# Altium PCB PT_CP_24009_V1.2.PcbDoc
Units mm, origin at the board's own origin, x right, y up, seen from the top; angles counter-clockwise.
Board outline 64.54 x 121.46 mm, 2 copper layers (Top Layer, Bottom Layer); 84 components, 67 nets, 226 pads, 45 vias.
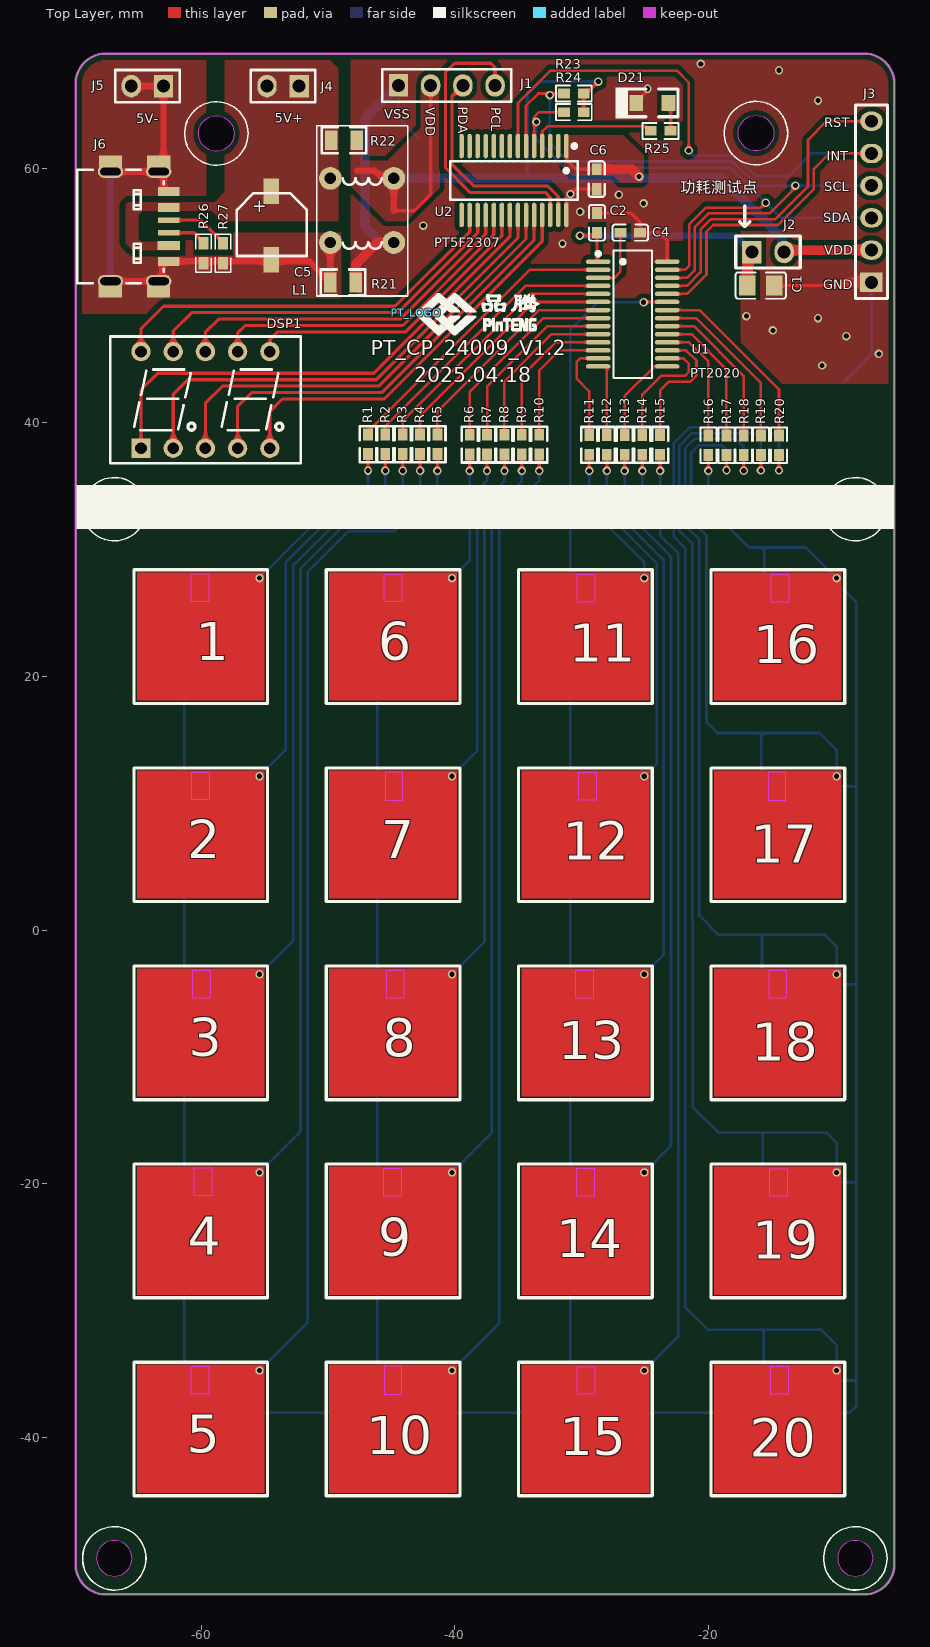
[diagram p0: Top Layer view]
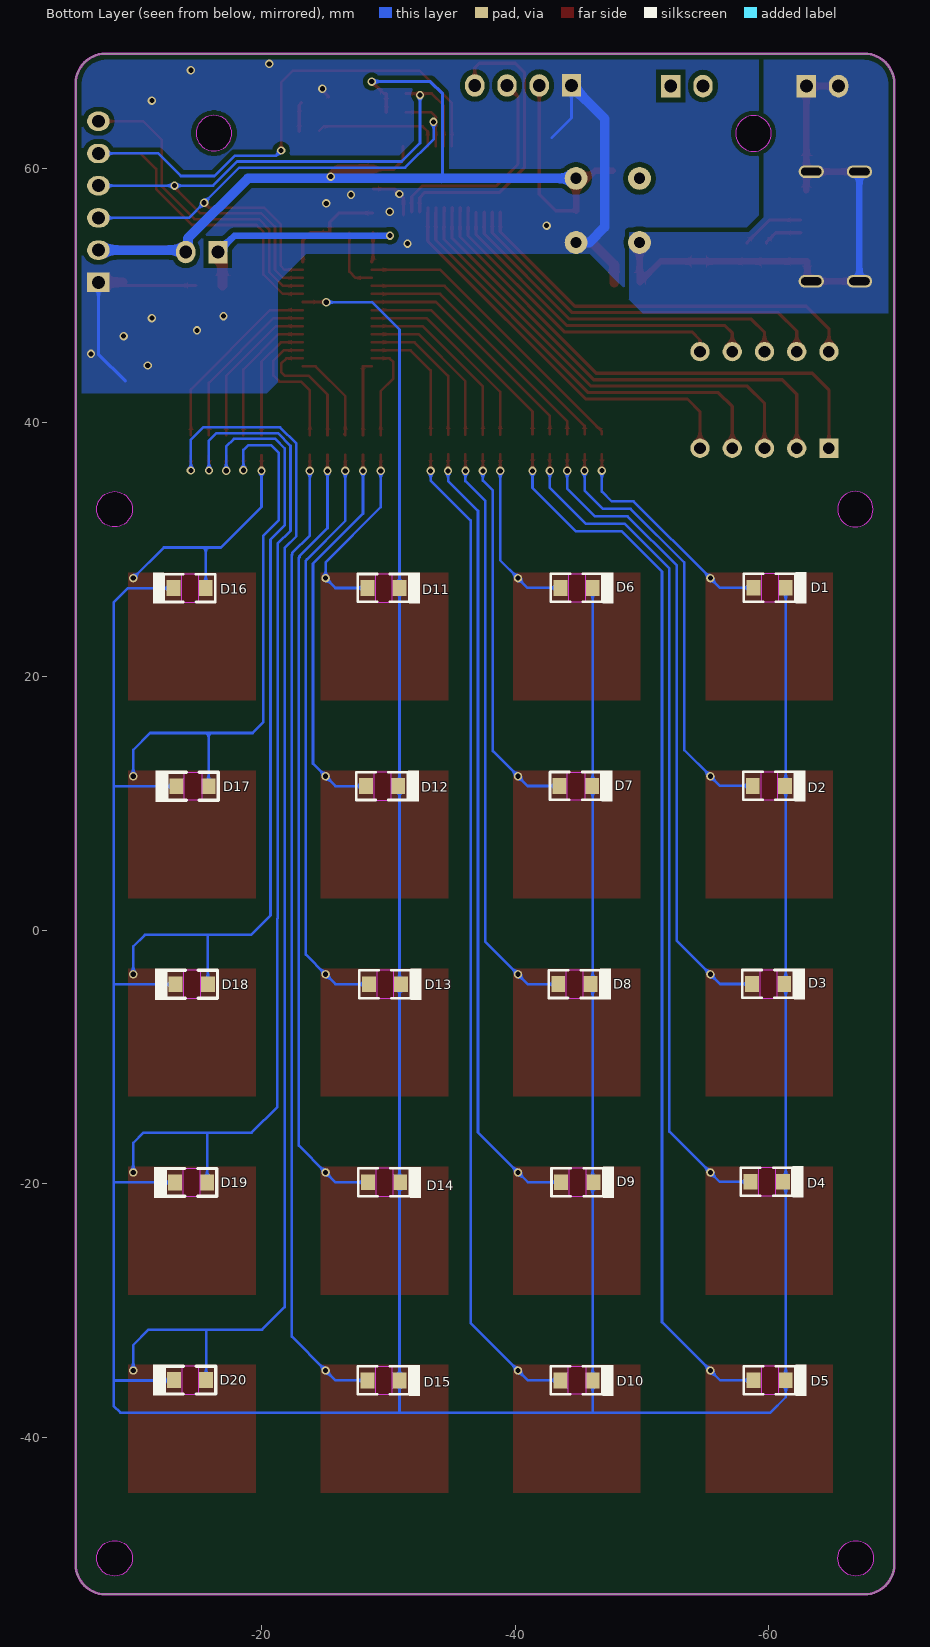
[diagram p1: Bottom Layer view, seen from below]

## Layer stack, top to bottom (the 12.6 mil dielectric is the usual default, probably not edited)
Top Solder: solder mask 0.0102, Solder Resist, Dk 3.5
Top Layer: signal copper 0.0356
Dielectric 1: dielectric 0.32, FR-4, Dk 4.8
Bottom Layer: signal copper 0.0356
Bottom Solder: solder mask 0.0102, Solder Resist, Dk 3.5

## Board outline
-69.901,-49.987 -69.901,66.7 cw(c-67.513,66.7) -67.513,69.088 -7.747,69.088 cw(c-7.747,66.7) -5.359,66.7 -5.359,-49.987 cw(c-7.747,-49.987) -7.747,-52.375 -67.513,-52.375 cw(c-67.513,-49.987)
cut-out: -60.782,25.868 -60.782,28.068 -59.411,28.068 -59.411,25.868
cut-out: -45.559,25.862 -45.559,28.062 -44.187,28.062 -44.187,25.862
cut-out: -30.336,25.855 -30.336,28.056 -28.964,28.056 -28.964,25.855
cut-out: -15.062,25.849 -15.062,28.049 -13.69,28.049 -13.69,25.849
cut-out: -60.723,10.254 -60.723,12.454 -59.351,12.454 -59.351,10.254
cut-out: -45.5,10.247 -44.128,10.247 -44.128,12.447 -45.5,12.447
cut-out: -30.226,10.241 -30.226,12.441 -28.854,12.441 -28.854,10.241
cut-out: -15.291,10.228 -13.919,10.228 -13.919,12.428 -15.291,12.428
cut-out: -60.664,-5.361 -60.664,-3.161 -59.292,-3.161 -59.292,-5.361
cut-out: -45.39,-5.367 -45.39,-3.167 -44.018,-3.167 -44.018,-5.367
cut-out: -30.454,-5.38 -30.454,-3.18 -29.083,-3.18 -29.083,-5.38
cut-out: -15.231,-5.386 -15.231,-3.186 -13.86,-3.186 -13.86,-5.386
cut-out: -60.553,-20.95 -60.553,-18.75 -59.182,-18.75 -59.182,-20.95
cut-out: -45.618,-20.989 -45.618,-18.788 -44.247,-18.788 -44.247,-20.989
cut-out: -30.395,-20.995 -30.395,-18.795 -29.024,-18.795 -29.024,-20.995
cut-out: -15.172,-21.001 -15.172,-18.801 -13.801,-18.801 -13.801,-21.001
cut-out: -60.782,-36.597 -60.782,-34.397 -59.411,-34.397 -59.411,-36.597
cut-out: -45.559,-36.603 -44.187,-36.603 -44.187,-34.403 -45.559,-34.403
cut-out: -30.336,-36.61 -30.336,-34.41 -28.964,-34.41 -28.964,-36.61
cut-out: -15.087,-36.59 -15.087,-34.39 -13.716,-34.39 -13.716,-36.59
cut-out: -66.827,31.772 cw(c-66.827,33.172) -68.227,33.172 cw(c-66.827,33.172) -66.827,34.572 cw(c-66.827,33.172) -65.427,33.172 cw(c-66.827,33.172)
cut-out: -9.833,33.172 ccw(c-8.433,33.172) -8.433,31.772 ccw(c-8.433,33.172) -7.033,33.172 ccw(c-8.433,33.172) -8.433,34.572 ccw(c-8.433,33.172)
cut-out: -58.801,61.389 cw(c-58.801,62.789) -60.201,62.789 cw(c-58.801,62.789) -58.801,64.189 cw(c-58.801,62.789) -57.401,62.789 cw(c-58.801,62.789)
cut-out: -16.267,61.414 cw(c-16.267,62.814) -17.667,62.814 cw(c-16.267,62.814) -16.267,64.214 cw(c-16.267,62.814) -14.867,62.814 cw(c-16.267,62.814)
cut-out: -68.25,-49.53 ccw(c-66.85,-49.53) -66.85,-50.93 ccw(c-66.85,-49.53) -65.45,-49.53 ccw(c-66.85,-49.53) -66.85,-48.13 ccw(c-66.85,-49.53)
cut-out: -9.833,-49.53 ccw(c-8.433,-49.53) -8.433,-50.93 ccw(c-8.433,-49.53) -7.033,-49.53 ccw(c-8.433,-49.53) -8.433,-48.13 ccw(c-8.433,-49.53)

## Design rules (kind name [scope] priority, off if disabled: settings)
Clearance [All] p1: gap=0.381
PolygonConnect [All] p1: connectstyle=Direct reliefconductorwidth=0.254 reliefentries=4 polygonreliefangle="90 Angle" airgapwidth=0.254
RoutingVias [All] p1: holewidth=0.711 width=1.27 viastyle="Through Hole" minholewidth=0.711 minwidth=1.27 maxholewidth=0.711 maxwidth=1.27
SolderMaskExpansion [All] p1: expansion=0.102
SupplyNets "Schematic Supply Nets_3" [InNet('GND')] p1: voltage=0.000
SupplyNets "Schematic Supply Nets_2" [InNet('IGND')] p2: voltage=0.000
SupplyNets "Schematic Supply Nets_1" [InNet('5V')] p3: voltage=0.000
SupplyNets "Schematic Supply Nets" [InNet('VIN')] p4: voltage=0.000
Width [All] p1: maxlimit=2.54 minlimit=0.203 preferedwidth=0.203
30 further rules are at their usual default settings.

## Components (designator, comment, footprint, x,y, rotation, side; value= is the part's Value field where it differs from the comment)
1 "DOWN" "TP_10mm - H" -60.046,23.165 r0 top
2 "DOWN" "TP_10mm - H" -60.046,7.55 r0 top
3 "DOWN" "TP_10mm - H" -60.046,-8.065 r0 top
4 "DOWN" "TP_10mm - H" -60.046,-23.679 r0 top
5 "DOWN" "TP_10mm - H" -60.046,-39.294 r0 top
6 "DOWN" "TP_10mm - H" -44.882,23.165 r0 top
7 "DOWN" "TP_10mm - H" -44.882,7.55 r0 top
8 "DOWN" "TP_10mm - H" -44.882,-8.065 r0 top
9 "DOWN" "TP_10mm - H" -44.882,-23.679 r0 top
10 "DOWN" "TP_10mm - H" -44.882,-39.294 r0 top
11 "DOWN" "TP_10mm - H" -29.718,23.165 r0 top
12 "DOWN" "TP_10mm - H" -29.718,7.55 r0 top
13 "DOWN" "TP_10mm - H" -29.718,-8.065 r0 top
14 "DOWN" "TP_10mm - H" -29.718,-23.679 r0 top
15 "DOWN" "TP_10mm - H" -29.718,-39.294 r0 top
16 "DOWN" "TP_10mm - H" -14.554,23.165 r0 top
17 "DOWN" "TP_10mm - H" -14.554,7.55 r0 top
18 "DOWN" "TP_10mm - H" -14.554,-8.065 r0 top
19 "DOWN" "TP_10mm - H" -14.554,-23.679 r0 top
20 "DOWN" "TP_10mm - H" -14.554,-39.294 r0 top
C1 "10uF" C0805 -16.942,50.8 r0 top
C2 "0.1uF" C0603 -28.804,54.966 r90 top
C4 "20nF" C0603 -25.4,54.966 r180 top
C5 "100uF/16V" CS5.0 -54.483,58.232 r90 top
C6 "0.1uF" C0603 -28.829,59.969 r270 top
D1 "LED_B" LED_0805_F -58.801,26.975 r180 bottom
D2 "LED_B" LED_0805_F -58.742,11.36 r180 bottom
D3 "LED_B" LED_0805_F -58.682,-4.254 r180 bottom
D4 "LED_B" LED_0805_F -58.572,-19.844 r180 bottom
D5 "LED_B" LED_0805_F -58.801,-35.49 r180 bottom
D6 "LED_B" LED_0805_F -43.578,26.968 r180 bottom
D7 "LED_B" LED_0805_F -43.519,11.354 r180 bottom
D8 "LED_B" LED_0805_F -43.409,-4.261 r180 bottom
D9 "LED_B" LED_0805_F -43.637,-19.882 r180 bottom
D10 "LED_B" LED_0805_F -43.578,-35.497 r180 bottom
D11 "LED_B" LED_0805_F -28.355,26.962 r180 bottom
D12 "LED_B" LED_0805_F -28.245,11.347 r180 bottom
D13 "LED_B" LED_0805_F -28.473,-4.274 r180 bottom
D14 "LED_B" LED_0805_F -28.414,-19.889 r180 bottom
D15 "LED_B" LED_0805_F -28.355,-35.503 r180 bottom
D16 "LED_B" LED_0805_F -15.621,26.955 r0 bottom
D17 "LED_B" LED_0805_F -15.85,11.335 r0 bottom
D18 "LED_B" LED_0805_F -15.79,-4.28 r0 bottom
D19 "LED_B" LED_0805_F -15.731,-19.895 r0 bottom
D20 "LED_B" LED_0805_F -15.646,-35.484 r0 bottom
D21 "LED_B" LED_0805 -23.165,65.202 r180 top
DSP1 "CS2821AS" LED_2_0.28_2281 -64.745,37.973 r0 top
J1 "4PIN" D2.54_4P -44.45,66.573 r0 top
J2 "2PIN" D2.54_2P -16.586,53.442 r0 top
J3 "6PIN" D2.54_6P -7.163,51.054 r90 top
J4 "2PIN" D2.54_2P -52.273,66.523 r180 top
J5 "2PIN" D2.54_2P -62.967,66.523 r180 top
J6 "Type-C母座" TYPE-C-6P -65.251,55.458 r90 top
L1 "NC" L_10*5 -44.814,54.195 r180 top
PT_LOGO "PT_LOGO" PT_LOGO_2 -43.053,48.641 r0 top
R1 "470R" R0603 -46.849,37.516 r90 top
R2 "470R" R0603 -45.481,37.516 r90 top
R3 "470R" R0603 -44.113,37.516 r90 top
R4 "470R" R0603 -42.745,37.516 r90 top
R5 "470R" R0603 -41.377,37.516 r90 top
R6 "470R" R0603 -38.837,37.49 r90 top
R7 "470R" R0603 -37.465,37.49 r90 top
R8 "470R" R0603 -36.093,37.49 r90 top
R9 "470R" R0603 -34.722,37.49 r90 top
R10 "470R" R0603 -33.35,37.49 r90 top
R11 "470R" R0603 -29.413,37.465 r90 top
R12 "470R" R0603 -28.016,37.465 r90 top
R13 "470R" R0603 -26.619,37.465 r90 top
R14 "470R" R0603 -25.222,37.465 r90 top
R15 "470R" R0603 -23.825,37.465 r90 top
R16 "470R" R0603 -20.015,37.44 r90 top
R17 "470R" R0603 -18.593,37.44 r90 top
R18 "470R" R0603 -17.234,37.44 r90 top
R19 "470R" R0603 -15.875,37.44 r90 top
R20 "470R" R0603 -14.453,37.44 r90 top
R21 "0R" R0805 -49.818,51.045 r0 top
R22 "0R" R0805 -49.733,62.255 r0 top
R23 "470R" R0603 -31.394,65.938 r0 top
R24 "470R" R0603 -31.394,64.465 r0 top
R25 "470R" R0603 -24.562,62.992 r0 top
R26 "5.1K" RES0603 -59.817,53.34 r90 top
R27 "5.1K" RES0603 -58.293,53.34 r90 top
U1 "PT2020P28" SSOP28_0.635 -28.702,52.68 r270 top
U2 "PT5F2306P28" SSOP28_0.635 -31.217,61.798 r180 top

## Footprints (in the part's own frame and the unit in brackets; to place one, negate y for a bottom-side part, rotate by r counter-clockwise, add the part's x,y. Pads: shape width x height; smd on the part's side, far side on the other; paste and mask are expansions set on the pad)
C0603 [mil]
  rect 36.69x30 smd: 1(0,0) 2(61,0)
  silkscreen extent -25,-25 86,25
C0805 [mm]
  rect 1.3x1.55 smd: 1(0,0) 2(2.102,0)
  silkscreen extent -0.93,-1.04 3.03,1.04
CS5.0 [mm] "贴片电解电容"
  rect 2x1.2 smd: 1(0,0) 2(-5.4,0)
  silkscreen extent -5.1,-2.8 -0.15,2.71
D2.54_2P [mil] "接线端子"
  rect 60x70 hole 40: 1(0,0)
  oval 60x70 hole 40: 2(100,0)
  silkscreen extent -50,-50 150,50
D2.54_4P [mil] "接线端子"
  rect 60x70 hole 40: 1(0,0)
  oval 60x70 hole 40: 2(100,0) 3(200,0) 4(300,0)
  silkscreen extent -50,-50 350,50
D2.54_6P [mil] "接线端子"
  rect 60x70 hole 40: 1(0,0)
  oval 60x70 hole 40: 2(100,0) 3(200,0) 4(300,0) 5(400,0) 6(500,0)
  silkscreen extent -50,-50 550,50
L_10*5 [mm] "共模电感"
  round 1.8 hole 0.889: 1(0,0) 2(5,0) 3(0,-5.055) 4(5,-5.055)
  silkscreen extent -1.09,-9.19 6.07,4.22
LED_2_0.28_2281 [mil] "2*8数码管"
  rect 60x60 hole 36 mask+2: 1(0,0)
  round 60 hole 36 mask+2: 2(100,0) 3(200,0) 4(300,0) 5(400,0) 6(400,300) 7(300,300) 8(200,300) 9(100,300) 10(0,300)
  silkscreen extent -95,-47 495,347
LED_0805 [mm]
  rect 1.1x1.25 smd mask+0.051: 1(0,0) 2(2.54,0)
  silkscreen extent -0.76,-1.23 4.17,1.23
LED_0805_F [mm]
  rect 1.1x1.25 smd mask+0.051: 1(0,0) 2(2.54,0)
  silkscreen extent -0.76,-1.23 4.17,1.23
PT_LOGO_2 [mm]
  silkscreen extent 0,-1.73 9.7,1.55
R0603 [mil]
  rect 36.69x30 smd: 1(0,0) 2(61,0)
  silkscreen extent -25,-25 86,25
R0805 [mm]
  rect 1x1.55 smd: 1(0,0) 2(2,0)
  silkscreen extent -0.75,-1.02 2.75,1.02
RES0603 [mil]
  rect 38x31 smd: 1(-31,0) 2(31,0)
  silkscreen extent -59,-24 59,24, body extent -30,-15 33,16, height 18
SSOP28_0.635 [mil]
  oval 14x76.17 smd: 1(0,0) 2(25,0) 3(50,0) 4(75,0) 5(100,0) 6(125,0) 7(150,0) 8(175,0) 9(200,0) 10(225,0) 11(250,0) 12(275,0) 13(300,0) 14(325,0) 15(325,213.93) 16(300,213.93) 17(275,213.93) 18(250,213.93) 19(225,213.93) 20(200,213.93) 21(175,213.93) 22(150,213.93) 23(125,213.93) 24(100,213.93) 25(75,213.93) 26(50,213.93) 27(25,213.93) 28(0,213.93)
  silkscreen extent -35,-6 360,167
"TP_10mm - H" [mil]
  round 26 hole 16: 1(183,180)
  Top Layer region: -197,-199 -197,197.5 198,197.5 198,-199
  silkscreen extent -207,-209 208,206
TYPE-C-6P [mm]
  rect 1.016x1.829 smd: 0(-5.073,-1.885) 0(-5.073,1.915) 0(5.073,-1.915) 0(5.073,1.885)
  oval 1x2 hole 0.6 slot 1.6 at 90 deg: 0(-4.32,-1.9) 0(-4.32,1.9) 0(4.32,-1.9) 0(4.32,1.9)
  rect 0.45x1.7 smd: A5(0.5,-2.7) B5(-0.5,-2.7)
  rect 0.7x1.8 smd: A9(-1.5,-2.7)
  rect 0.7x1.7 smd: A12(-2.75,-2.7) B9(1.5,-2.7) B12(2.75,-2.7)
  silkscreen extent -4.47,-2.3 4.47,4.5

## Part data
1 2 3 4 5 6 7 8 9 10 11 12 13 14 15 16 17 18 19 20: library part TOUCH_SM, "TP"
C1 C2 C4: library part CAP3
C5: library part CAP2, "电解电容"
C6: library part CAP1, "电容"
D1 D2 D3 D4 D5 D6 D7 D8 D9 D10 D11 D12 D13 D14 D15 D16 D17 D18 D19 D20 D21: library part LED
DSP1: library part LED_2, "2位数码管"
J6: library part Type-C-receptacle_6p, "Type-C 6P直插"
L1: library part "Trans Cupl", "Transformer (Coupled Inductor Model)"
R1 R2 R3 R4 R5 R6 R7 R8 R9 R10 R11 R12 R13 R14 R15 R16 R17 R18 R19 R20 R21 R22 R23 R24 R25: library part RES1, "电阻"
R26 R27: library part Res, "Resistor"
U1: "20键标品"
U2: library part PT109AP28, "MCU"

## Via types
v1: diameter 0.66, hole 0.406, Top Layer to Bottom Layer, tented both sides, 45 vias

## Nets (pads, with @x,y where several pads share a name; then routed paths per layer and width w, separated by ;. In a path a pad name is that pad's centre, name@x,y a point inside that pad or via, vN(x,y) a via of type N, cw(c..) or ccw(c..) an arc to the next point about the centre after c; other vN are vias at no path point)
5V: C6.1 J1.2 J2.2 J3.2 L1.3 R22.2 R23.2 R24.2 U2.1 | length 87.5
  Top Layer w0.254: -44.814,56.695 -43.203,56.695 -41.91,57.988 J1.2 ; U2.1@-31.166,61.798 -31.166,60.725 -31.188,60.703 -30.455,59.969 C6.1 ; R24.2 R23.2 -29.642,65.938 v1(-28.702,66.878)
  Top Layer w0.508: -47.716,59.859 -46.321,59.859 -44.814,58.352 -44.814,56.695
  Top Layer w0.762: C6.1 -26.06,59.969 v1(-25.476,59.385) ; J2.2@-14.021,53.823 -13.792,53.594 J3.2
  Bottom Layer w0.254: -34.239,59.249 -34.29,59.3 -34.29,65.913 -33.325,66.878 v1(-28.702,66.878)
  Bottom Layer w0.762: L1.3 -34.239,59.249 -18.94,59.249 -14.224,54.534 -14.224,54.026 -13.792,53.594 J3.2
CC1: J6.A5 R27.2 | length 5.1
  Top Layer w0.254: J6.A5 -60.035,55.958 -58.293,54.216 R27.2
CC2: J6.B5 R26.2 | length 3.1
  Top Layer w0.254: J6.B5 -60.559,54.958 -59.817,54.216 R26.2
GND: C1.2 C2.2 C4.1 C6.2 D21.2 J1.1 J3.1 L1.1 R21.2 U1.28 U2.28 | length 56.7
  Top Layer w0.203: D21.2@-25.324,65.659 v1@-24.74,66.243
  Top Layer w0.254: U2.28 -31.217,57.683 v1(-30.886,58.014) -30.48,58.42 C6.2 ; C2.2 -26.111,56.515 -25.4,55.804 C4.1 -23.876,54.966 -23.268,54.358 U1.28 ; C1.2 -7.417,50.8 J3.1
  Top Layer w0.762: R21.2 -47.818,52.461 -46.084,54.195 L1.1 ; -9.068,51.054 J3.1
  Bottom Layer w0.203: J1.1 -44.45,64.008 -42.901,62.459
  Bottom Layer w0.254: -9.271,43.282 -7.163,45.39 J3.1
  Bottom Layer w0.762: L1.1 -45.864,54.195 -47.066,55.397 -47.066,63.957 J1.1
  other v1: -11.049,44.501 -6.579,45.415 -9.144,46.812 -14.935,47.269 -11.379,48.235 -17.018,48.387 -31.521,54.102 -42.494,55.524 -30.124,56.617 -25.121,57.277 -27.076,57.963 -11.379,65.38 -24.816,66.319 -14.453,67.767 -20.625,68.275
I2C_SCL: J3.4 R23.1 U1.26 U2.6 | length 53.2
  Top Layer w0.203: U2.6 -34.392,64.973 -33.426,65.938 R23.1 ; U1.26 -21.717,51.41 -21.082,52.045 -21.082,55.421 -20.013,56.49 -15.215,56.49 -13.157,58.547 v1(-13.157,58.674)
  Bottom Layer w0.203: v1(-32.512,65.811) -32.512,62.027 -31.064,60.579 -18.099,60.579 -16.194,58.674 -12.243,58.674 ; v1(-13.157,58.674) -12.243,58.674 ; J3.4 -12.243,58.674
I2C_SDA: J3.3 R24.1 U1.27 U2.5 | length 47
  Top Layer w0.203: U2.5 -33.757,64.084 -33.376,64.465 R24.1 ; U1.27 -21.844,52.045 -21.539,52.349 -21.539,55.61 -20.202,56.947 -15.875,56.947 v1(-15.494,57.328)
  Bottom Layer w0.203: v1(-33.579,63.703) -33.579,62.332 -31.344,60.096 -18.263,60.096 v1(-15.494,57.328) -14.3,56.134 J3.3
IGND: C5.2 J5.1 J5.2 J6.0 J6.A12 J6.B12 L1.2 R21.1 R26.1 R27.1 | length 46
  Top Layer w0.508: J6.0@-67.151,51.138 -65.557,51.138 -63.451,51.138 -63.051,51.538 -63.051,52.708 -60.452,52.708 -59.69,52.708 -58.928,52.708 -58.547,52.708 -57.556,52.708 -54.737,52.708 -51.481,52.708 R21.1 -49.818,54.191 L1.2 ; J6.0@-67.151,59.778 -63.451,59.778 J6.0@-63.082,59.778 ; J5.2 J5.1 J6.B12@-62.967,58.293
  Bottom Layer w0.508: J6.0@-67.151,51.138 J6.0@-67.151,59.778
INT: J3.5 U1.24 U2.7 | length 63.2
  Top Layer w0.203: U2.7 -35.027,65.176 -32.461,67.742 -22.504,67.742 -21.565,66.802 v1(-21.565,61.443) ; U1.24 -21.692,50.14 -20.168,51.664 -20.168,55.042 -19.634,55.575 -14.543,55.575 -11.709,58.408 -11.709,59.995 -10.49,61.214 J3.5
  Bottom Layer w0.203: v1(-21.565,61.443) -21.158,61.036 -17.909,61.036 -16.309,59.436 -13.665,59.436 -11.887,61.214 J3.5
LED_A: DSP1.7 U2.19 | length 26.7
  Top Layer w0.254: DSP1.7 -57.125,47.066 -56.54,47.65 -44.087,47.65 -36.932,54.806 U2.19@-36.932,56.593
LED_B: DSP1.8 U2.18 | length 28.5
  Top Layer w0.254: DSP1.8 -59.665,47.117 -58.623,48.158 -44.298,48.158 -37.567,54.889 U2.18@-37.567,56.593
LED_C: DSP1.3 U2.23 | length 36.7
  Top Layer w0.254: DSP1.3 -59.665,41.529 -58.318,42.875 -45.989,42.875 -34.392,54.472 U2.23@-34.392,56.593 ; U2.23@-34.417,56.593 U2.23@-34.417,56.949
LED_COM: D1.2 D2.2 D3.2 D4.2 D5.2 D6.2 D7.2 D8.2 D9.2 D10.2 D11.2 D12.2 D13.2 D14.2 D15.2 D16.2 D17.2 D18.2 D19.2 D20.2 U1.23 | length 364.2
  Top Layer w0.203: v1@-25.095,49.505 U1.23
  Bottom Layer w0.203: D1.2 D5.2 -61.341,-36.83 -60.122,-38.049 -8.89,-38.049 -8.357,-37.516 -8.357,11.354 ; -46.118,-38.041 D6.2 ; -30.895,-38.032 D11.2 -30.895,47.337 -28.753,49.479 v1(-25.121,49.479) ; D17.2 -8.376,11.335 -8.357,11.354 ; D18.2 -8.395,-4.28 ; D19.2 -8.414,-19.895 ; D20.2 -13.106,-35.509 -8.382,-35.509 ; D16.2 -13.075,26.949 -9.5,26.949 -8.357,25.806 -8.357,11.354
LED_D: DSP1.2 U2.22 | length 38.9
  Top Layer w0.254: DSP1.2 -62.205,42.24 -61.062,43.383 -46.199,43.383 -35.027,54.556 U2.22@-35.027,56.593 ; U2.22@-35.052,56.593 U2.22@-35.052,56.949
LED_DP: DSP1.5 U2.25 | length 32.6
  Top Layer w0.254: DSP1.5 -54.585,40.869 -53.594,41.859 -45.568,41.859 -33.122,54.305 U2.25@-33.122,56.593 ; U2.25@-33.147,56.593 U2.25@-33.147,56.949
LED_E: DSP1.1 U2.21 | length 41
  Top Layer w0.254: DSP1.1 -64.745,42.57 -63.424,43.891 -46.41,43.891 -35.662,54.639 U2.21@-35.662,56.593 ; U2.21@-35.687,56.593 U2.21@-35.687,56.949
LED_F: DSP1.10 U2.16 | length 32.4
  Top Layer w0.254: DSP1.10 -64.745,47.396 -62.967,49.174 -44.718,49.174 -38.837,55.056 U2.16@-38.837,56.593
LED_G: DSP1.4 U2.24 | length 34.7
  Top Layer w0.254: DSP1.4 -57.125,41.275 -56.032,42.367 -45.778,42.367 -33.757,54.389 U2.24@-33.757,56.593 ; U2.24@-33.782,56.593 U2.24@-33.782,56.949
LED_G1: DSP1.9 U2.17 | length 30.5
  Top Layer w0.254: DSP1.9 -62.205,47.219 -60.757,48.666 -44.508,48.666 -38.202,54.973 U2.17@-38.202,56.593
LED_G2: DSP1.6 U2.20 | length 24.8
  Top Layer w0.254: DSP1.6 -54.585,46.507 -53.95,47.142 -43.877,47.142 -36.297,54.723 U2.20@-36.297,56.593 ; U2.20@-36.322,56.593 U2.20@-36.322,56.949
MCU_RX0: J1.4 U2.26 | length 23.7
  Top Layer w0.254: J1.4 -36.83,67.97 -37.186,68.326 -40.03,68.326 -40.742,67.615 -40.742,60.071 -38.811,58.141 -32.893,58.141 -32.487,57.734 U2.26@-32.487,56.593
MCU_TX0: J1.3 U2.27 | length 17.6
  Top Layer w0.254: J1.3@-39.37,66.192 J1.3 -40.234,65.71 -40.234,60.376 -38.506,58.649 -32.683,58.649 -31.852,57.818 U2.27@-31.852,56.593
Net1_1: 1.1 D1.1 R1.1 | length 18.1
  Top Layer w0.203: v1(-46.849,36.209) R1.1
  Bottom Layer w0.203: D1.1 -56.159,26.975 1.1 -49.352,33.782 -47.625,33.782 -46.849,34.558 v1(-46.849,36.209)
Net2_1: 2.1 D2.1 R2.1 | length 34.4
  Top Layer w0.203: v1(-45.481,36.206) R2.1
  Bottom Layer w0.203: D2.1 -56.159,11.36 2.1 -53.34,14.18 -53.34,28.968 -49.11,33.198 -46.943,33.198 -45.481,34.66 v1(-45.481,36.206)
Net3_1: 3.1 D3.1 R3.1 | length 50.8
  Top Layer w0.203: v1(-44.113,36.202) R3.1
  Bottom Layer w0.203: D3.1 -56.159,-4.254 3.1 -52.756,-0.851 -52.756,28.726 -48.868,32.614 -46.304,32.614 -44.113,34.805 v1(-44.113,36.202)
Net4_1: 4.1 D4.1 R4.1 | length 67.1
  Top Layer w0.203: v1(-42.745,36.199) R4.1
  Bottom Layer w0.203: D4.1 -56.134,-19.844 4.1 -52.172,-15.881 -52.172,28.484 -48.626,32.029 -45.568,32.029 -42.745,34.852 v1(-42.745,36.199)
Net5_1: 5.1 D5.1 R5.1 | length 83.9
  Top Layer w0.203: v1(-41.377,36.195) R5.1
  Bottom Layer w0.203: D5.1 -56.166,-35.49 5.1 -51.587,-30.912 -51.587,28.242 -48.384,31.445 -44.78,31.445 -41.377,34.849 v1(-41.377,36.195)
Net6_1: 6.1 D6.1 R6.1 | length 14
  Top Layer w0.203: v1(-38.837,36.195) R6.1
  Bottom Layer w0.203: D6.1 -41.002,26.968 6.1 -38.837,29.134 v1(-38.837,36.195)
Net7_1: 7.1 D7.1 R7.1 | length 30.1
  Top Layer w0.203: v1(-37.465,36.195) R7.1
  Bottom Layer w0.203: D7.1 -41.002,11.354 7.1 -38.252,14.103 -38.252,34.646 -37.465,35.433 v1(-37.465,36.195)
Net8_1: 8.1 D8.1 R8.1 | length 46.2
  Top Layer w0.203: v1(-36.093,36.195) R8.1
  Bottom Layer w0.203: D8.1 -41.002,-4.261 8.1 -37.668,-0.927 -37.668,33.807 -36.093,35.382 v1(-36.093,36.195)
Net9_1: 9.1 D9.1 R9.1 | length 62.6
  Top Layer w0.203: v1(-34.722,36.195) R9.1
  Bottom Layer w0.203: D9.1 -41.008,-19.882 9.1 -37.084,-15.958 -37.084,33.045 -34.722,35.408 v1(-34.722,36.195)
Net10_1: 10.1 D10.1 R10.1 | length 78.7
  Top Layer w0.203: v1(-33.35,36.195) R10.1
  Bottom Layer w0.203: D10.1 -41.008,-35.497 10.1 -36.5,-30.988 -36.5,32.283 -33.35,35.433 v1(-33.35,36.195)
Net11_1: 11.1 D11.1 R11.1 | length 15.1
  Top Layer w0.203: v1(-29.413,36.195) R11.1
  Bottom Layer w0.203: v1(-29.413,36.195) -29.413,33.325 -25.07,28.981 11.1 -25.845,26.962 D11.1
Net12_1: 12.1 D12.1 R12.1 | length 30.9
  Top Layer w0.203: v1(-28.016,36.195) R12.1
  Bottom Layer w0.203: D12.1 -25.845,11.347 12.1 -24.079,13.113 -24.079,28.88 -28.016,32.817 v1(-28.016,36.195)
Net13_1: 13.1 D13.1 R13.1 | length 46.6
  Top Layer w0.203: v1(-26.619,36.195) R13.1
  Bottom Layer w0.203: D13.1 -25.851,-4.274 13.1 -23.52,-1.943 -23.52,29.111 -23.597,29.187 -23.597,29.223 -26.619,32.246 v1(-26.619,36.195)
Net14_1: 14.1 D14.1 R14.1 | length 62
  Top Layer w0.203: v1(-25.222,36.195) R14.1
  Bottom Layer w0.203: D14.1 -25.851,-19.889 14.1 -22.962,-16.999 -22.962,29.343 -23.012,29.394 -23.012,29.465 -25.222,31.675 v1(-25.222,36.195)
Net15_1: 15.1 D15.1 R15.1 | length 77.5
  Top Layer w0.203: v1(-23.825,36.195) R15.1
  Bottom Layer w0.203: D15.1 -25.851,-35.503 15.1 -22.403,-32.055 -22.403,29.574 -22.428,29.6 -22.428,29.707 -23.825,31.104 v1(-23.825,36.195)
Net16_1: 16.1 D16.1 R16.1 | length 19.7
  Top Layer w0.203: v1(-20.015,36.195) R16.1
  Bottom Layer w0.203: v1(-20.015,36.195) -20.015,33.35 -16.815,30.15 -15.621,30.15 ; D16.1 -15.621,30.15 ; 16.1 -12.319,30.15 -15.621,30.15
Net17_1: 17.1 D17.1 R17.1 | length 45.2
  Top Layer w0.203: v1(-18.593,36.246) R17.1
  Bottom Layer w0.203: v1(-18.593,36.246) -18.593,37.846 -18.974,38.227 -20.777,38.227 -21.387,37.617 -21.387,32.309 -20.168,31.09 -20.168,16.383 -19.317,15.532 -11.239,15.532 -9.906,14.199 17.1 ; D17.1 -15.85,15.532
Net18_1: 18.1 D18.1 R18.1 | length 63.5
  Top Layer w0.203: v1(-17.234,36.208) R18.1
  Bottom Layer w0.203: v1(-17.234,36.208) -17.234,38.113 -17.831,38.71 -21.11,38.71 -21.844,37.975 -21.844,31.902 -20.726,30.785 -20.726,1.143 -19.202,-0.381 -15.799,-0.381 ; D18.1 -15.79,-0.389 -15.799,-0.381 ; 18.1 -9.906,-1.295 -10.82,-0.381 -15.799,-0.381
Net19_1: 19.1 D19.1 R19.1 | length 82
  Top Layer w0.203: v1(-15.875,36.22) R19.1
  Bottom Layer w0.203: v1(-15.875,36.22) -15.875,38.583 -16.459,39.167 -21.299,39.167 -22.301,38.165 -22.301,31.471 -21.285,30.455 -21.285,0.912 -21.26,0.886 -21.26,-13.945 -19.228,-15.977 -10.719,-15.977 -9.906,-16.789 19.1 ; D19.1 -15.731,-15.994
Net20_1: 20.1 D20.1 R20.1 | length 100.5
  Top Layer w0.203: v1(-14.453,36.22) R20.1
  Bottom Layer w0.203: D20.1 -15.646,-31.547 -15.596,-31.496 ; v1(-14.453,36.22) -14.453,38.659 -15.418,39.624 -21.488,39.624 -22.758,38.354 -22.758,31.039 -21.844,30.124 -21.844,-29.718 -20.066,-31.496 -15.596,-31.496 ; 20.1 -9.906,-32.715 -11.125,-31.496 -15.596,-31.496
NetC1_1: C1.1 C2.1 J2.1 U1.1 | length 20.3
  Top Layer w0.254: v1(-30.15,54.737) C2.1@-29.032,54.737 ; C2.1 -28.804,52.832 U1.1@-28.702,52.73 ; U1.1@-28.727,52.705 U1.1
  Top Layer w0.762: C1.1 -16.942,53.086 J2.1
  Bottom Layer w0.508: v1(-30.15,54.737) -17.882,54.737 J2.1
NetC4_2: C4.2 U1.3 | length 5
  Top Layer w0.203: U1.3 -27.432,51.41 -26.949,51.892 C4.2
NetD21_1: D21.1 R25.2 | length 2.3
  Top Layer w0.254: D21.1 -22.987,65.024 R25.2@-22.987,62.941
OUT: R25.1 U2.4 | length 10
  Top Layer w0.203: U2.4 -33.122,62.941 -32.715,63.348 -25.832,63.348 -24.917,63.348 R25.1
RST: J3.6 U1.25 | length 25.6
  Top Layer w0.203: U1.25 -21.705,50.775 -20.625,51.855 -20.625,55.231 -19.824,56.032 -14.732,56.032 -12.167,58.598 -12.167,62.281 -10.693,63.754 J3.6
TCH1: R1.2 U1.2 | length 23.7
  Top Layer w0.203: R1.2 -46.849,39.308 -34.112,52.045 U1.2
TCH2: R2.2 U1.4 | length 22
  Top Layer w0.203: R2.2 -45.481,39.736 -34.442,50.775 U1.4
TCH3: R3.2 U1.5 | length 20.6
  Top Layer w0.203: R3.2 -44.113,40.114 -34.087,50.14 U1.5
TCH4: R4.2 U1.6 | length 19.2
  Top Layer w0.203: R4.2 -42.745,40.517 -33.757,49.505 U1.6
TCH5: R5.2 U1.7 | length 17.8
  Top Layer w0.203: R5.2 -41.377,40.869 -33.376,48.87 U1.7
TCH6: R6.2 U1.8 | length 15.9
  Top Layer w0.203: R6.2 -38.837,42.418 -33.02,48.235 U1.8
TCH7: R7.2 U1.9 | length 14.5
  Top Layer w0.203: R7.2 -37.465,42.85 -32.715,47.6 U1.9
TCH8: R8.2 U1.10 | length 13.1
  Top Layer w0.203: R8.2 -36.093,43.256 -32.385,46.965 U1.10
TCH9: R9.2 U1.11 | length 11.8
  Top Layer w0.203: R9.2 -34.722,43.688 -32.08,46.33 U1.11
TCH10: R10.2 U1.12 | length 10.4
  Top Layer w0.203: R10.2 -33.35,44.12 -31.775,45.695 U1.12
TCH11: R11.2 U1.13 | length 8
  Top Layer w0.203: R11.2 -29.413,42.469 -30.404,43.459 -30.404,44.78 -30.124,45.06 U1.13
TCH12: R12.2 U1.14 | length 6.1
  Top Layer w0.203: U1.14 -28.016,44.425 R12.2
TCH13: R13.2 U1.15 | length 7.5
  Top Layer w0.203: R13.2@-26.543,39.091 R13.2 -26.619,42.088 -24.282,44.425 U1.15
TCH14: R14.2 U1.16 | length 10.1
  Top Layer w0.203: R14.2 -25.222,42.215 -23.749,43.688 -21.869,43.688 -21.565,43.993 -21.565,44.653 -21.971,45.06 U1.16
TCH15: R15.2 U1.17 | length 10.7
  Top Layer w0.203: R15.2 -23.825,42.52 -23.114,43.231 -21.438,43.231 -20.955,43.713 -20.955,44.882 -21.768,45.695 U1.17
TCH16: R16.2 U1.18 | length 9.7
  Top Layer w0.203: U1.18 -21.539,46.33 -20.015,44.806 R16.2
TCH17: R17.2 U1.19 | length 11
  Top Layer w0.203: U1.19 -21.361,46.965 -18.593,44.196 R17.2
TCH18: R18.2 U1.20 | length 12.3
  Top Layer w0.203: U1.20 -21.158,47.6 -17.234,43.675 R18.2
TCH19: R19.2 U1.21 | length 13.6
  Top Layer w0.203: U1.21 -20.98,48.235 -15.875,43.129 R19.2
TCH20: R20.2 U1.22 | length 15
  Top Layer w0.203: U1.22 -20.701,48.87 -14.453,42.621 R20.2
VIN: C5.1 J4.1 J4.2 J6.A9 J6.B9 L1.4 R22.1
pads on no net: U2.2 U2.3 U2.8 U2.9 U2.10 U2.11 U2.12 U2.13 U2.14 U2.15

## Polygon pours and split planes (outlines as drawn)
GND on Top Layer "Top Layer-No Net" (solid, remove dead copper, pour order 48): -48.215,60.569 -48.215,69.078 -7.239,69.078 -6.151,68.444 -5.441,67.28 -5.365,67.204 -5.365,43.068 -15.677,43.068 -17.506,44.897 -17.481,44.923 -17.481,52.027 -17.481,54.312 -17.481,55.241 -17.506,54.338 -23.12,54.338 -23.12,51.679 -24.872,49.926 -24.974,49.825 -40.693,49.825 -47.333,49.825 -48.323,50.815 -48.215,50.924
5V on Top Layer "Top Layer-No Net 1" (solid, pour order 46): -31.09,62.662 -26.721,62.662 -25.349,61.29 -25.121,61.062 -25.121,59.08 -25.121,59.055 -25.273,58.903 -26.213,58.903 -26.949,58.903 -27.457,59.411 -27.559,59.512 -29.21,59.512 -30.759,59.512 -31.344,60.096 -31.394,60.147 -31.394,62.484 -31.394,62.611 -31.344,62.662 -31.09,62.662
5V on Top Layer "Top Layer-No Net" (solid, remove dead copper, pour order 4): -41.199,66.599 -41.199,58.522 -43.688,56.032 -43.866,55.855 -45.187,55.855 -45.441,55.855 -46.507,56.921 -48.209,58.623 -48.209,61.849 -47.269,61.849 -47.269,60.63 -45.314,60.63 -43.383,62.56 -42.697,63.246 -42.697,66.599 -41.224,66.599 -41.199,66.573
VIN on Top Layer "VIN_L01_P049" (hatched Horizontal grid 0 track 0.1, remove dead copper, pour order 49): -49.2,55.88 -49.2,67.92 -49.876,68.596 -58.141,68.596 -58.141,58.166 -58.928,57.378 -65.735,57.378 -65.964,57.15 -65.964,54.141 -65.401,53.578 -61.789,53.578 -61.773,53.594 -61.773,54.229 -64.694,54.229 -64.948,54.483 -64.948,56.388 -64.694,56.642 -59.106,56.642 -58.344,55.88
IGND on Top Layer "IGND_L01_P050" (hatched Horizontal grid 0 track 0.1, remove dead copper, pour order 50): -49.022,54.991 -58.42,54.991 -59.614,56.185 -59.614,69.063 -59.627,69.075 -68.513,69.075 -69.952,67.637 -69.952,48.616 -50.063,48.616 -48.971,49.708 -48.971,54.94
IGND on Bottom Layer "Top Layer-No Net" (solid, remove dead copper, pour order 16): -60.3,69.088 -68.478,69.088 -69.901,67.666 -69.952,67.615 -69.952,63.043 -69.952,48.616 -63.983,48.616 -50.063,48.616 -48.971,49.708 -49.022,49.759 -49.022,54.991 -58.42,54.991 -59.309,55.88 -59.614,56.185 -59.614,64.211 -59.614,69.063 -59.639,69.088 -60.325,69.088
GND on Bottom Layer "Top Layer-No Net" (solid, remove dead copper, pour order 42): -69.902,48.738 -69.902,67.484 -70.003,67.585 -68.53,69.058 -7.291,69.058 -7.037,69.058 -6.91,69.058 -5.538,67.687 -5.411,67.56 -5.411,42.312 -20.422,42.312 -20.626,42.515 -21.282,43.172 -21.282,46.228 -21.282,51.054 -23.532,53.303 -38.557,53.303 -45.88,53.303 -46.788,52.396 -47.956,51.228 -48.482,50.702 -49.328,49.856 -50.445,48.738 -51.156,48.738 -68.997,48.738

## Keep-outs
Keep-Out Layer:
  the board outline again, w0.203

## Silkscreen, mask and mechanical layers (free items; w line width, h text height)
Top Overlay:
  circle w0.127: c-8.433,33.172 r2.5
  circle w0.127: c-66.85,33.172 r2.5
  circle w0.127: c-66.85,-49.53 r2.5
  circle w0.127: c-8.433,-49.53 r2.5
  circle w0.127: c-16.267,62.814 r2.5
  circle w0.127: c-58.801,62.789 r2.5
  rectangle: -69.825,31.623 -5.385,35.077
  lines w0.254: -17.551,55.829 -17.17,55.448 ; -17.145,57.074 -17.145,55.448 -16.764,55.829
  text "PDA" at -39.751,64.897 h0.76 r270
  text "VDD" at -42.291,64.846 h0.76 r270
  text "PCL" at -37.135,64.846 h0.76 r270
  text "VSS" at -45.568,63.932 h0.76
  text "5V+" at -54.204,63.652 h0.76
  text "5V-" at -65.1,63.576 h0.76
  text "RST" at -10.897,63.297 h0.76
  text "INT" at -10.668,60.63 h0.76
  text "SCL" at -10.897,58.242 h0.76
  text "功耗测试点" at -22.225,57.785 h1.52
  text "SDA" at -10.973,55.778 h0.76
  text "PT5F2307" at -41.631,53.823 h0.76
  text "VDD" at -10.897,53.213 h0.76
  text "GND" at -10.947,50.495 h0.76
  text "PT_CP_24009_V1.2" at -46.632,44.911 h2.03
  text "PT2020" at -21.463,43.536 h0.76
  text "2025.04.18" at -43.203,42.798 h2.03
Mechanical 1:
  circle w0.127: c-8.433,33.172 r1.4
  circle w0.127: c-66.85,-49.53 r1.4
  circle w0.127: c-8.433,-49.53 r1.4
  circle w0.127: c-66.827,33.172 r1.4
  circle w0.127: c-16.267,62.814 r1.4
  circle w0.127: c-58.801,62.789 r1.4
  lines w0.127: -60.782,-36.597 -60.782,-34.397 -59.411,-34.397 -59.411,-36.597 -60.782,-36.597 ; -60.782,25.868 -60.782,28.068 -59.411,28.068 -59.411,25.868 -60.782,25.868 ; -60.723,10.254 -60.723,12.454 -59.351,12.454 -59.351,10.254 -60.723,10.254 ; -60.664,-5.361 -60.664,-3.161 -59.292,-3.161 -59.292,-5.361 -60.664,-5.361 ; -60.553,-20.95 -60.553,-18.75 -59.182,-18.75 -59.182,-20.95 -60.553,-20.95 ; -45.618,-20.989 -45.618,-18.788 -44.247,-18.788 -44.247,-20.989 -45.618,-20.989 ; -45.559,-36.603 -45.559,-34.403 -44.187,-34.403 -44.187,-36.603 -45.559,-36.603 ; -45.559,25.862 -45.559,28.062 -44.187,28.062 -44.187,25.862 -45.559,25.862 ; -45.5,10.247 -45.5,12.447 -44.128,12.447 -44.128,10.247 -45.5,10.247 ; -45.39,-5.367 -45.39,-3.167 -44.018,-3.167 -44.018,-5.367 -45.39,-5.367 ; -30.454,-5.38 -30.454,-3.18 -29.083,-3.18 -29.083,-5.38 -30.454,-5.38 ; -30.395,-20.995 -30.395,-18.795 -29.024,-18.795 -29.024,-20.995 -30.395,-20.995 ; -30.336,-36.61 -30.336,-34.41 -28.964,-34.41 -28.964,-36.61 -30.336,-36.61 ; -30.336,25.855 -30.336,28.056 -28.964,28.056 -28.964,25.855 -30.336,25.855 ; -30.226,10.241 -30.226,12.441 -28.854,12.441 -28.854,10.241 -30.226,10.241 ; -15.291,10.228 -15.291,12.428 -13.919,12.428 -13.919,10.228 -15.291,10.228 ; -15.231,-5.386 -15.231,-3.186 -13.86,-3.186 -13.86,-5.386 -15.231,-5.386 ; -15.172,-21.001 -15.172,-18.801 -13.801,-18.801 -13.801,-21.001 -15.172,-21.001 ; -15.087,-36.59 -15.087,-34.39 -13.716,-34.39 -13.716,-36.59 -15.087,-36.59 ; -15.062,25.849 -15.062,28.049 -13.69,28.049 -13.69,25.849 -15.062,25.849
  lines w0.203: -69.901,-49.987 ccw(c-67.513,-49.987) -67.513,-52.375 -7.747,-52.375 ccw(c-7.747,-49.987) -5.359,-49.987 -5.359,66.7 ccw(c-7.747,66.7) -7.747,69.088 -67.513,69.088 ccw(c-67.513,66.7) -69.901,66.7 -69.901,-49.987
